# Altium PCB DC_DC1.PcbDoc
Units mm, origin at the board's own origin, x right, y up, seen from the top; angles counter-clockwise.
Board outline 93.09 x 48.26 mm, 2 copper layers (Top Layer, Bottom Layer); 19 components, 7 nets, 46 pads, 1 vias.
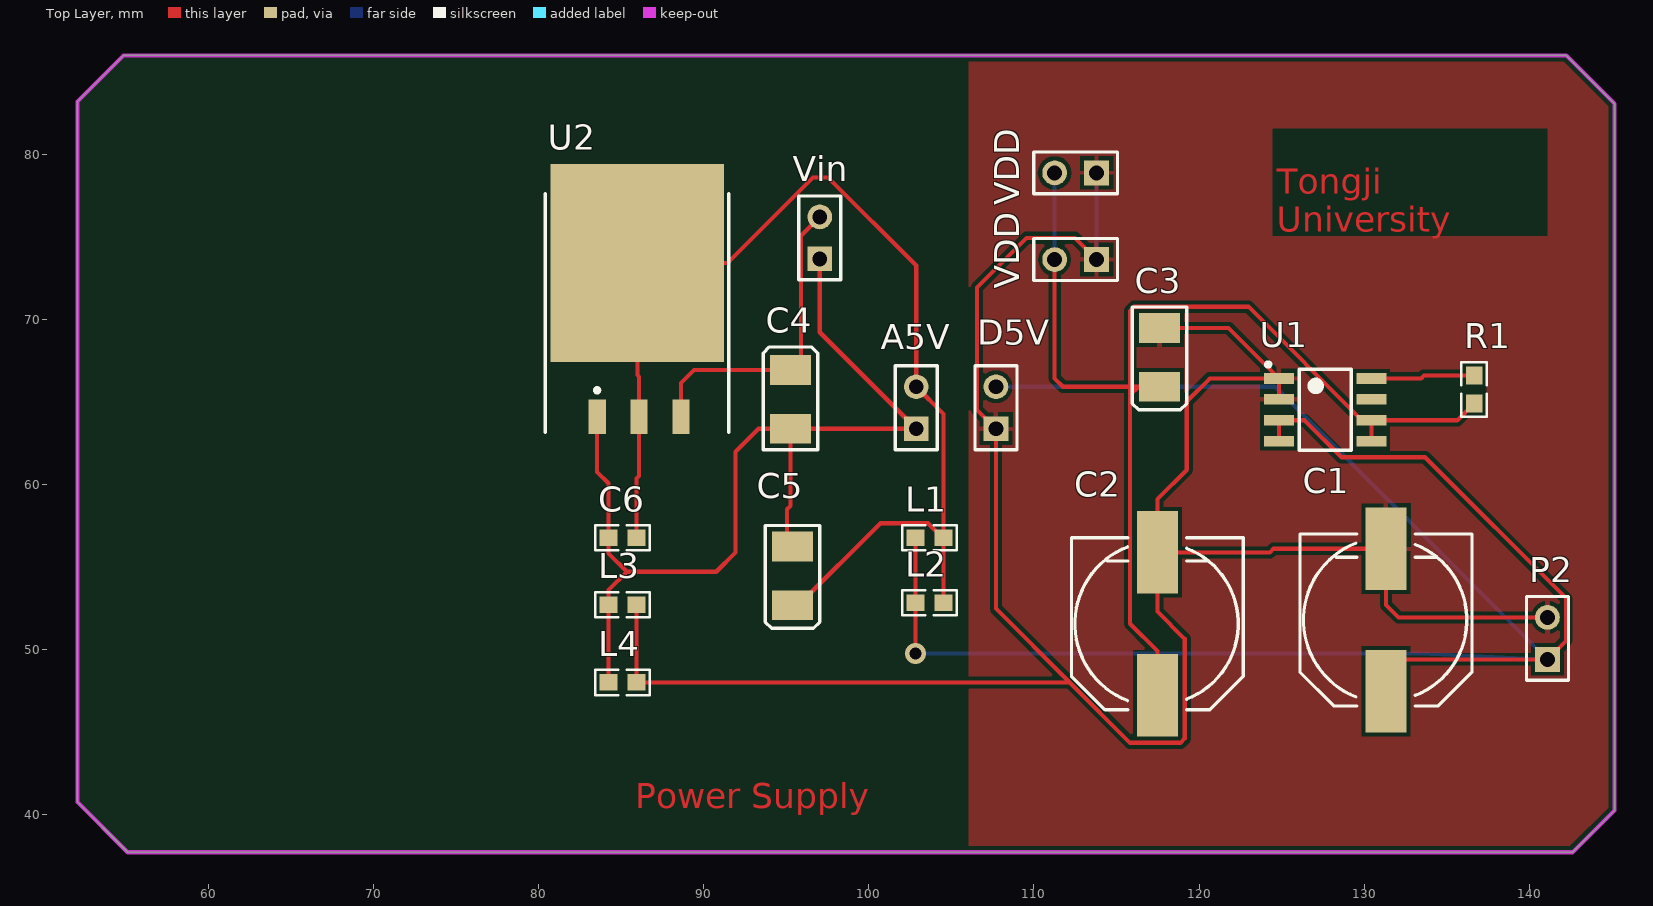
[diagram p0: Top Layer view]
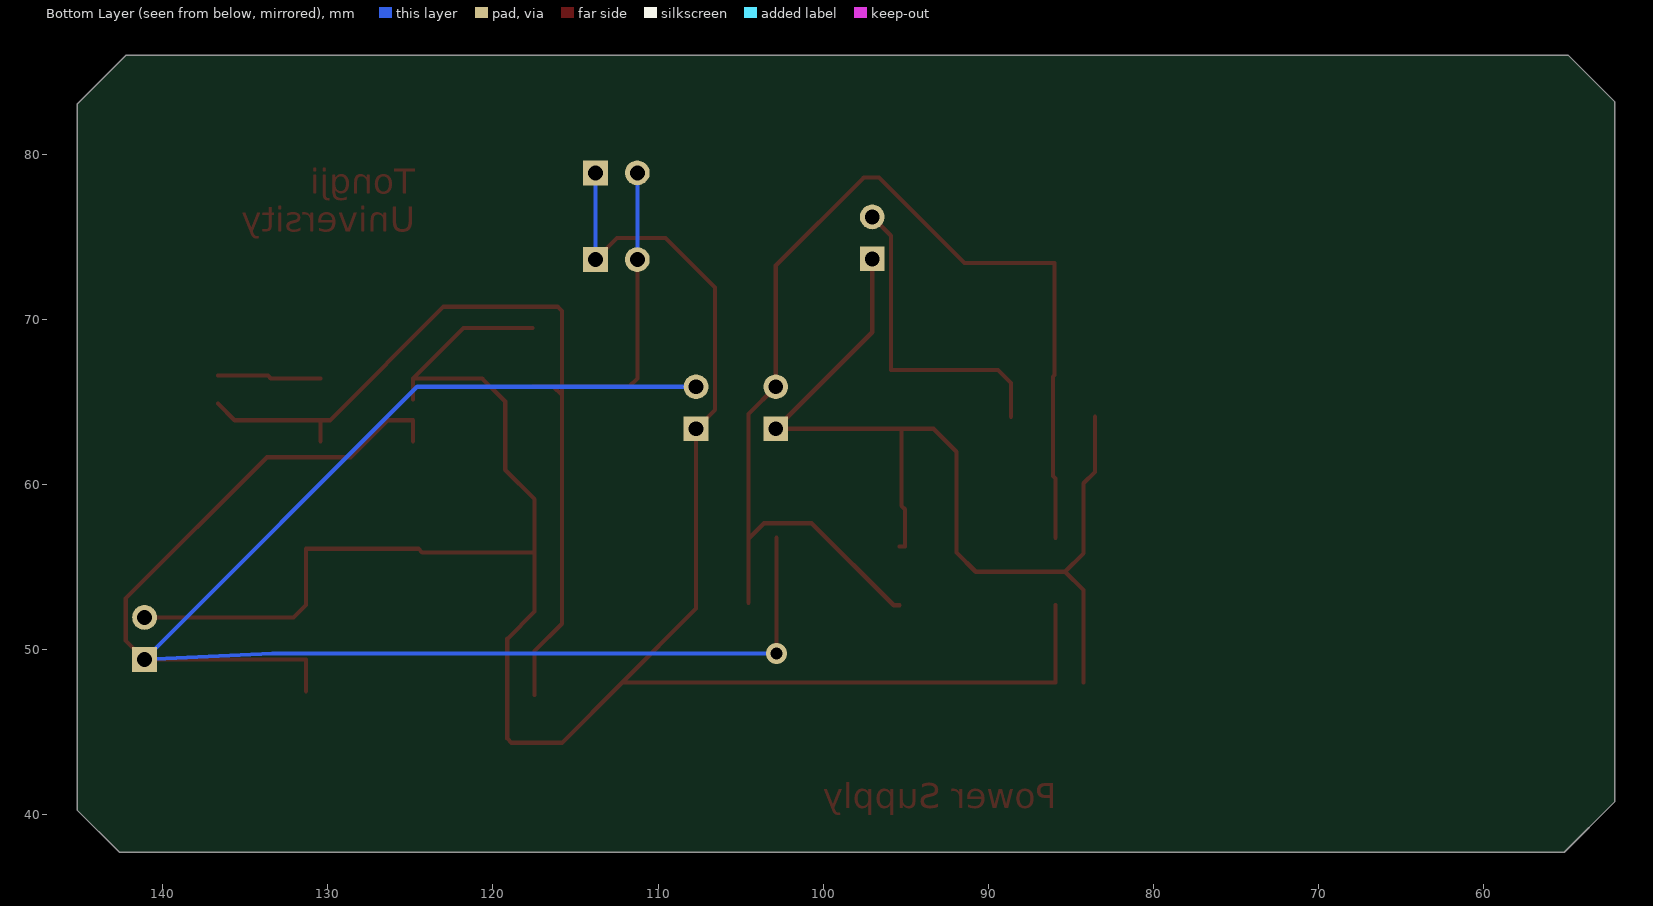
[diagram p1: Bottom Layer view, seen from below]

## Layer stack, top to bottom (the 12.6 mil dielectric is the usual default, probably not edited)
Top Solder: solder mask 0.0102, Solder Resist, Dk 3.5
Top Layer: signal copper 0.0356
Dielectric 1: dielectric 0.32, FR-4, Dk 4.8
Bottom Layer: signal copper 0.0356
Bottom Solder: solder mask 0.0102, Solder Resist, Dk 3.5

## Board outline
52.07,40.767 55.118,37.719 142.621,37.719 145.161,40.259 145.161,83.058 142.24,85.979 54.864,85.979 52.07,83.185

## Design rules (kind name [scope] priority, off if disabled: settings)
Clearance [All] p1: gap=0.254 ignorepadtopadclearanceinfootprint=FALSE except(0: Arc-Hole Track-Hole SMDPad-Hole THPad-Hole Via-Hole Fill-Hole Poly-Hole Region-Hole Text-Hole)
PolygonConnect [All] p1: connectstyle=Relief reliefconductorwidth=0.254 reliefentries=4 polygonreliefangle="90 Angle" airgapwidth=0.254
RoutingVias [All] p1: holewidth=0.711 width=1.27 viastyle="Through Hole" minholewidth=0.711 minwidth=1.27 maxholewidth=0.711 maxwidth=1.27
SolderMaskExpansion [All] p1: expansion=0.102
Width [All] p1: maxlimit=0.254 minlimit=0.254 preferedwidth=0.254
30 further rules are at their usual default settings.

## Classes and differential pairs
component class DC_DC: A5V C1 C2 C3 C4 C5 C6 D5V L1 L2 L3 L4 P2 R1 U1 U2 Vin

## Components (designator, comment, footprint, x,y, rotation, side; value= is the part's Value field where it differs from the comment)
A5V "Analog" HDR1X2 102.87,63.373 r90 top (schematic designator P6)
C1 "10uF/16V" C-RB-SD10 131.318,51.791 r90 top value=10uF
C2 "0.1uF/16V" C-RB-SD10 117.475,51.562 r90 top value=0.1uF
C3 "CT-22uF/16V" CAP-3528 117.602,67.691 r90 top
C4 "CT-22uF/16V" CAP-3528 95.25,65.151 r270 top
C5 "CT-22uF/16V" CAP-3528 95.377,54.458 r90 top
C6 "C-0.1uF/16V" 0603-1 85.08,56.769 r0 top value=100nF
D5V "Digital" HDR1X2 107.696,63.373 r90 top (schematic designator P5)
L1 "L-MB" 0603-1 103.671,56.769 r0 top
L2 "L-MB" 0603-1 103.671,52.832 r0 top
L3 "L-MB" 0603-1 85.08,52.705 r180 top
L4 "L-MB" 0603-1 85.08,48.006 r180 top
P2 "Header 2" HDR1X2 141.097,49.403 r90 top
R1 "249k" 0603-1 136.652,65.747 r270 top value=1K
U1 "U-TPS76833QD" SOIC8 127.635,64.516 r0 top
U2 "U-LM1085" TO263-3 86.083,68.326 r0 top
VDD "Header 2" HDR1X2 113.792,78.867 r180 top (schematic designator P4)
VDD "Header 2" HDR1X2 113.792,73.618 r180 top (schematic designator P3)
Vin "V in" HDR1X2 97.028,73.66 r90 top (schematic designator P7)

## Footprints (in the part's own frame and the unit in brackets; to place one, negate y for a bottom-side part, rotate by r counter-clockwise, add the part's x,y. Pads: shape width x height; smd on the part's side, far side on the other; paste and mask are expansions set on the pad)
0603-1 [mm] "0603带丝印"
  rect 1.1x1 smd: 1(-0.85,0) 2(0.85,0)
  silkscreen extent -1.65,-0.76 1.65,0.76, body extent -0.8,-0.4 0.8,0.4, height 0.3
C-RB-SD10 [mm] "贴片铝电解"
  rect 5x2.5 smd: 1(-4.318,0) 2(4.318,0)
  silkscreen extent -5.21,-5.21 5.21,5.21, body extent -5.21,-5.21 5.21,5.21, height 10.5
CAP-3528 [mm] "钽电容"
  rect 1.8x2.5 smd: 1(-1.778,0) 2(1.778,0)
  silkscreen extent -3.17,-1.65 3.05,1.65, body extent -1.91,-1.4 1.91,1.4, height 1.1
HDR1X2 [mm] "Connector; Header; 2 Position"
  rect 1.5x1.5 hole 0.9: 1(0,0)
  round 1.5 hole 0.9: 2(2.54,0)
  silkscreen extent -1.27,-1.27 3.81,1.27
SOIC8 [mm] "SOIC,1.27mm pitch;8 pin,3.90mm W X 4.88mm L X 1.73mm H body"
  rect 1.8x0.65 smd: 1(-2.8,1.905) 2(-2.8,0.635) 3(-2.8,-0.635) 4(-2.8,-1.905) 5(2.8,-1.905) 6(2.8,-0.635) 7(2.8,0.635) 8(2.8,1.905)
  silkscreen extent -3.57,-2.45 1.58,2.87, body extent -3.11,-2.45 3.11,2.45, height 1.75
TO263-3 [mm] "LM2940/LM1086"
  rect 1.05x2.1 smd: 1(-2.54,-4.225) 2(0,-4.225) 3(2.54,-4.225)
  rect 10.5x12 smd: 2(-0.104,5.08)
  silkscreen extent -5.68,-5.17 5.42,9.28, body extent -5.46,-4.7 5.21,9.27, height 1.6

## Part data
A5V D5V Vin: library part "Header 2", "Header, 2-Pin"
C1 C2: library part "Cap Pol2", "Polarized Capacitor (Axial)"
C3: "钽电容"
C4 C5: library part Cap-Pol-A, "钽电容"
C6: library part Cap, "Capacitor"
L1 L2 L3 L4: library part Res2, "Resistor"
P2 VDD VDD: "Header, 2-Pin"
R1: library part Res3, "Resistor"
U1: library part TPS76850
U2: library part LM1085

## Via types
v1: diameter 1.27, hole 0.711, Top Layer to Bottom Layer, 1 vias

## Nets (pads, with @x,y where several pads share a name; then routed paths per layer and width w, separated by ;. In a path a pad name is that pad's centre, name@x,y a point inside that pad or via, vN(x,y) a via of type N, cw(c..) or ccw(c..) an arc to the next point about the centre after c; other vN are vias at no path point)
DC+3.3V: C2.1 C3.1 R1.2 U1.5 U1.6 VDD.2 | length 69.2
  Top Layer w0.254: VDD.2@111.252,73.618 111.252,66.421 111.76,65.913 115.824,65.913 ; C2.1 117.475,49.911 115.824,51.562 115.824,65.405 ; C3.1 116.332,65.913 ; U1.5 U1.6 ; R1.2 135.636,63.881 U1.6 ; 115.824,65.405 115.824,65.913 ; 115.824,65.405 116.332,65.913 ; 115.824,65.913 116.332,65.913 ; 115.824,65.913 115.824,70.51 116.078,70.764 122.987,70.764 129.87,63.881 U1.6
  Bottom Layer w0.254: VDD.2@111.252,73.618 VDD.2@111.252,78.867
DC+5V: C1.1 D5V.2 L1.1 L2.1 P2.1 U1.3 U1.4 | length 124.5
  Top Layer w0.254: v1(102.821,49.759) L2.1 L1.1 ; U1.4 U1.3 126.39,63.881 128.626,61.646 133.68,61.646 142.24,53.086 142.24,50.546 P2.1 131.318,49.403 C1.1
  Bottom Layer w0.254: v1(102.821,49.759) 133.362,49.759 P2.1 124.587,65.913 D5V.2
DC+5V_ANALOG: A5V.2 C5.1 C6.2 L1.2 L2.2 U2.2 | length 70.7
  Top Layer w0.254: C6.2 85.93,60.35 86.083,60.504 86.083,64.101 86.083,66.523 85.979,66.627 85.979,73.406 91.44,73.406 96.622,78.588 97.536,78.588 102.87,73.254 A5V.2 104.521,64.262 L1.2 ; C5.1 95.727,52.68 100.697,57.65 103.59,57.65 104.471,56.769 L1.2 ; L2.2 L1.2
GND: C1.2 C2.2 C3.2 D5V.1 L3.1 L4.1 P2.2 U1.1 U1.2 VDD.1 | length 145.2
  Top Layer w0.254: L3.1 85.93,50.343 L4.1 112.166,48.006 ; VDD.1@113.792,73.618 112.48,74.93 109.55,74.93 106.553,71.933 106.553,64.516 D5V.1 107.696,52.476 112.166,48.006 ; C3.2 121.787,69.469 U1.1 ; U1.2 U1.1 ; P2.2 132.08,51.943 131.318,52.705 C1.2 124.511,56.109 124.282,55.88 C2.2 ; 112.166,48.006 115.824,44.348 118.872,44.348 119.126,44.602 119.126,50.648 117.475,52.299 C2.2 ; C2.2 117.475,59.106 119.253,60.884 119.253,65.024 120.65,66.421 U1.1
  Bottom Layer w0.254: VDD.1@113.792,73.618 VDD.1@113.792,78.867
IGND: A5V.1 C4.2 C5.2 C6.1 L3.2 L4.2 U2.1 Vin.1 | length 62.2
  Top Layer w0.254: U2.1 83.543,60.758 84.23,60.071 C6.1 84.23,55.826 85.344,54.712 ; L4.2 84.23,50.343 L3.2 84.23,53.598 85.344,54.712 ; C5.2 95.044,56.236 95.044,58.496 95.25,58.702 C4.2 ; Vin.1 97.028,69.215 A5V.1 C4.2 ; 85.344,54.712 90.754,54.712 91.923,55.88 91.923,61.976 93.32,63.373 C4.2
NetR1_1: R1.1 U1.8 | length 6.3
  Top Layer w0.254: U1.8 133.452,66.421 133.628,66.597 R1.1
VCC_RAW: C4.1 U2.3 Vin.2 | length 19.4
  Top Layer w0.254: U2.3 88.623,66.144 89.408,66.929 C4.1 95.885,66.929 95.885,75.057 Vin.2
pads on no net: U1.7

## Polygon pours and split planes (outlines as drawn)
GND on Bottom Layer (solid, pour order 10): 104.521,85.852
GND on Top Layer "GND_L01_P020" (solid, remove dead copper, pour order 20): 105.791,85.979 106.045,85.725 106.045,37.719 142.367,37.719 144.907,40.259 145.161,40.259 145.161,83.058 142.24,85.979

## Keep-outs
Top Layer:
  lines w0.254: 52.07,40.767 55.118,37.719 59.055,37.719 142.621,37.719 145.161,40.259 145.161,83.058 142.24,85.979 54.864,85.979 52.07,83.185 52.07,40.767

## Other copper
Top Layer:
  text "Tongji  / University" at 124.714,75.311 h1.52
  text "Power Supply" at 85.852,40.386 h1.52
